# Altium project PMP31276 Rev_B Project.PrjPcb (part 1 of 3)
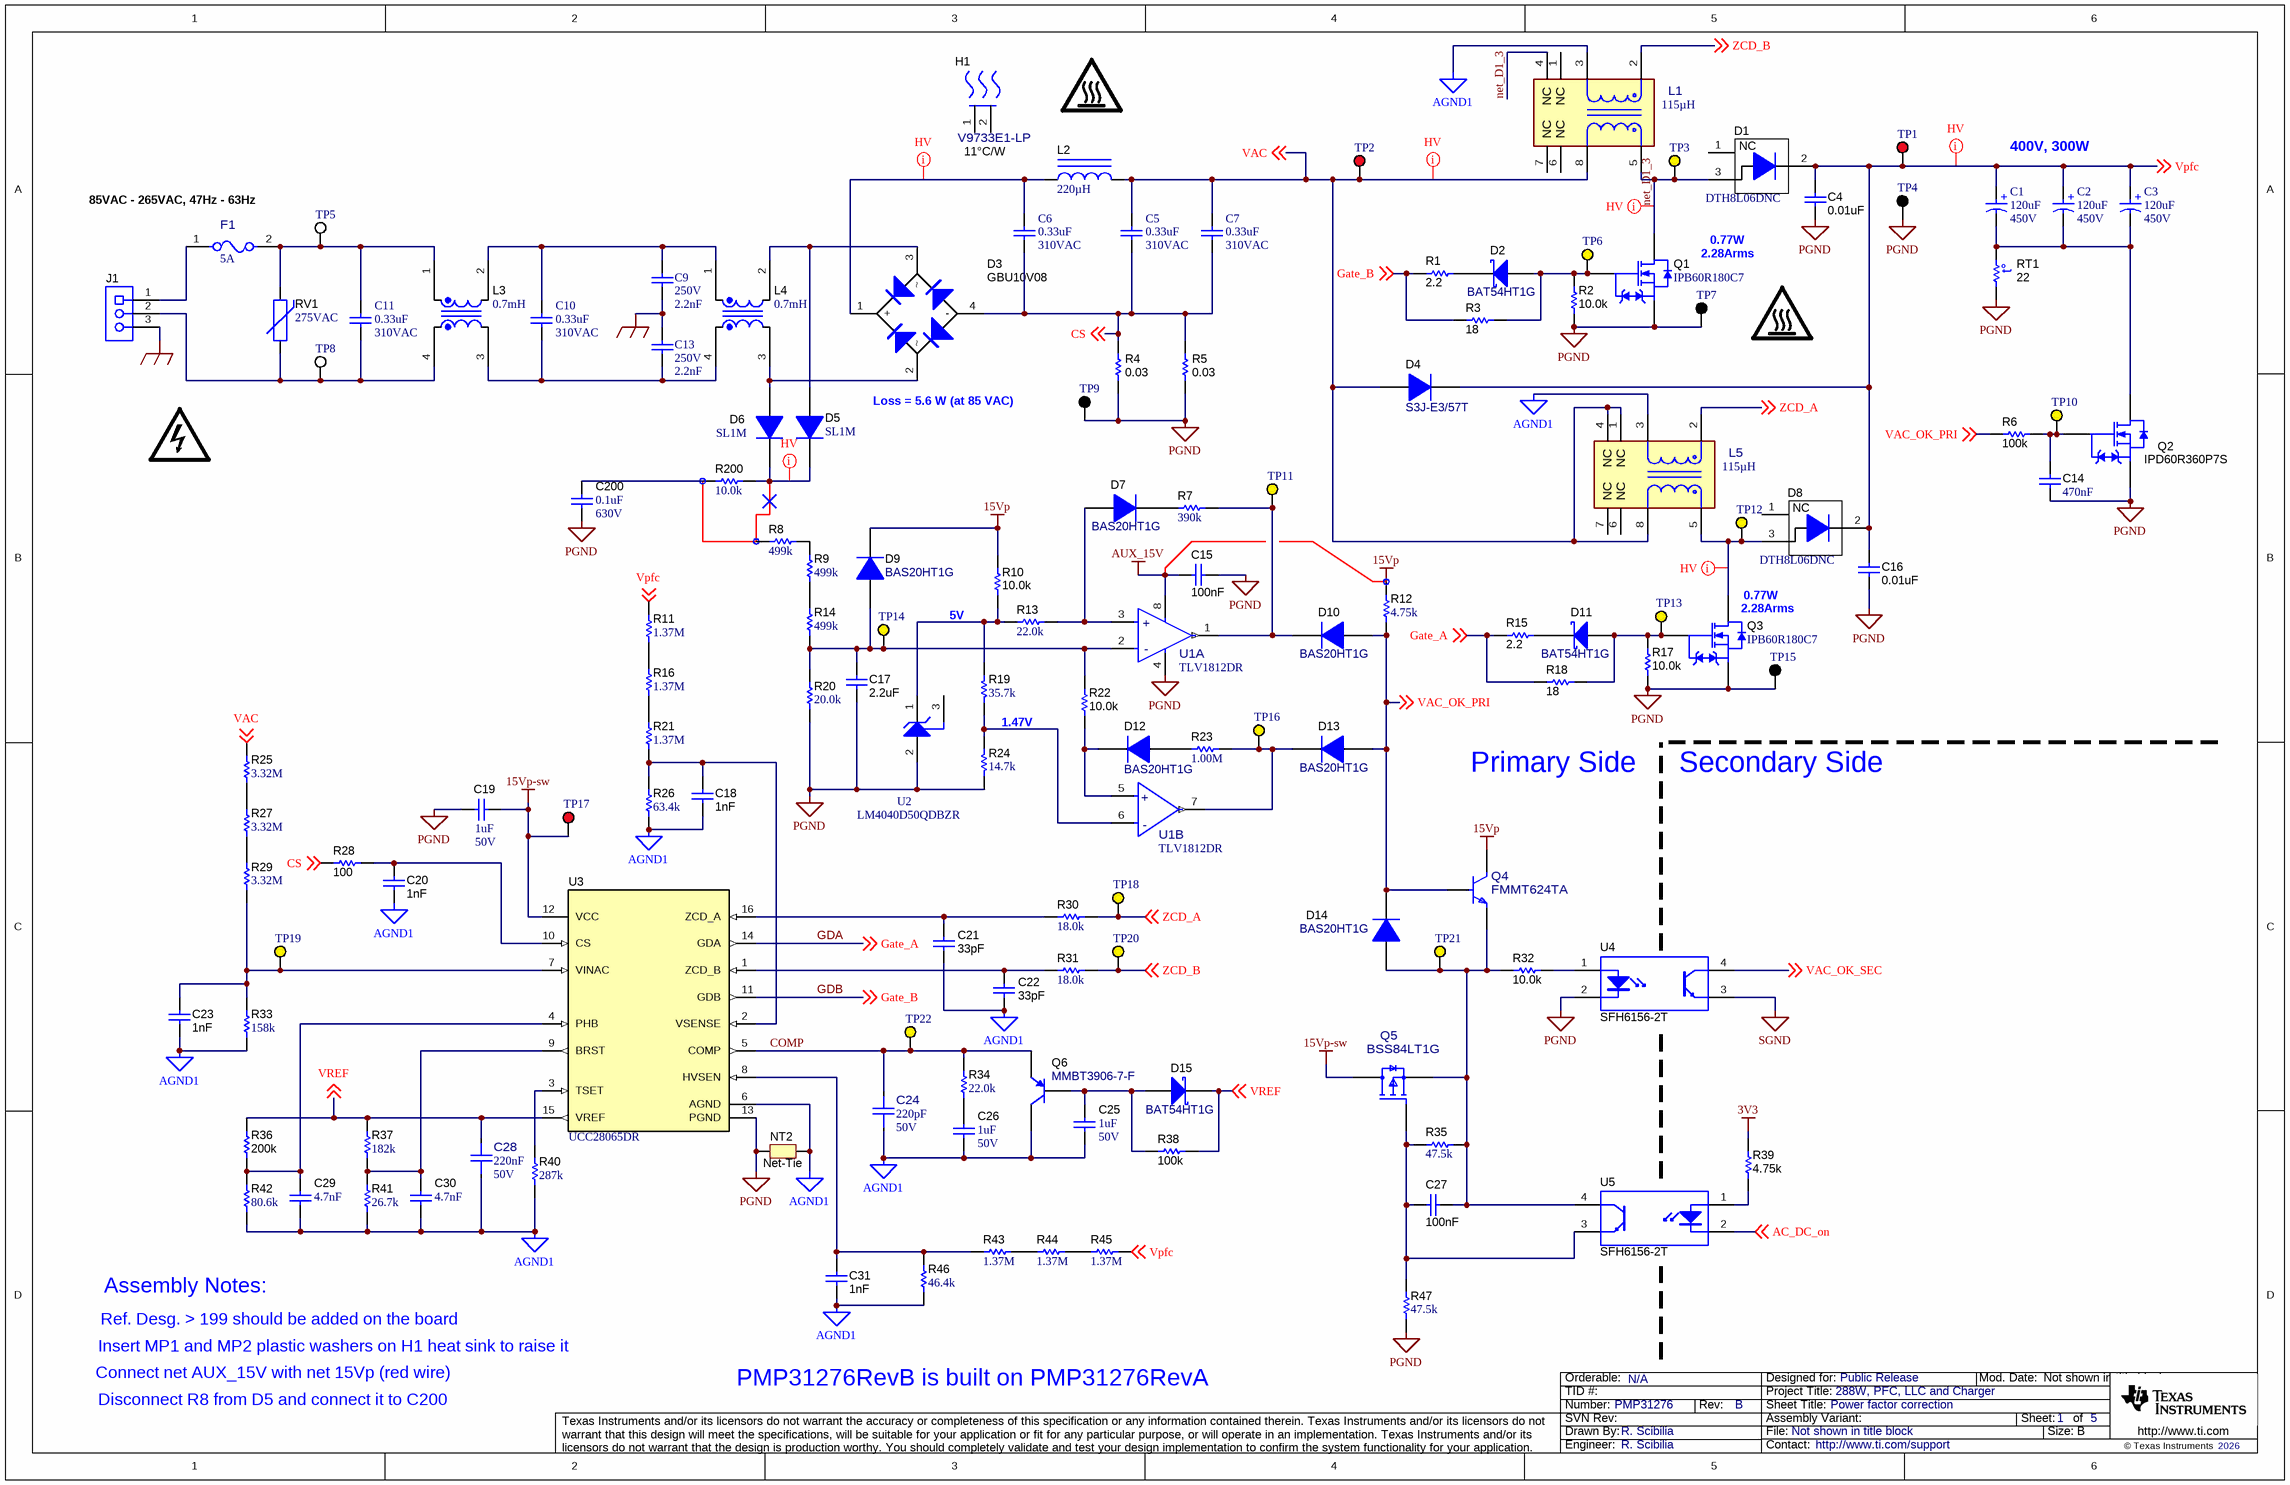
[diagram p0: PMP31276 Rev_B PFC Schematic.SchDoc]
CopyrightYear: 2026; EVM_orderable: N/A; PCB_Layout: N/A; PCB_Rev: A; PRJ_Customer: Public Release; PRJ_Engineer: R. Scibilia; PRJ_Number: PMP31276; PRJ_Title: 288W, PFC, LLC and Charger; SCH_Rev: B; TechSupport: http://www.ti.com/support
5 sheets, 390 parts. Net scope: global (net labels, ports and power ports of the same name join across sheets).
Board file: PMP31276 Rev_A PCB.PcbDoc
Sheets:
  PMP31276 Rev_B PFC Schematic.SchDoc
  PMP31276 Rev_B LLC Schematic.SchDoc
  PMP31276 Rev_B Charger Schematic.SchDoc
  PMP31276 Rev_B LaunchPad Schematic.SchDoc
  PMP31276 Rev_B Hardware.SchDoc

## Sheet PMP31276 Rev_B PFC Schematic.SchDoc: Power factor correction
size 431 x 279 mm; Date: Not shown in title block; ApprovedBy: Not shown in title block; CheckedBy: Not shown in title block; Author: Not shown in title block; CompanyName: Not shown in title block; DrawnBy: R. Scibilia; Engineer: R. Scibilia; Organization: Not shown in title block; Address1: Not shown in title block; Address2: Not shown in title block; Address3: Not shown in title block; Address4: Not shown in title block; DocumentNumber: 1; Revision: Use project parameter SCH_Rev; SheetNumber: 1; SheetTotal: 5; PageSetup: Record=PageOptions¦CenterHorizontal=True¦CenterVertical=True¦PrintScale=1.00¦XCorrection=1.00¦YCorrection=1.00¦PrintKind=0¦BorderSize=5000000¦LeftOffset=0¦BottomOffset=0¦Orientation=2¦PaperLength=1000¦PaperWidth=1000¦Scale=100¦PaperSource=15¦PrintQuality=600¦MediaType=1¦DitherType=10¦PaperKind=Letter¦PrintScaleMode=1

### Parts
(Parts that share a designator on the sheet are numbered #1, #2 ... from top to bottom, then left to right.)
C1  value 120uF  Rated Voltage (DC): 450V  [WCAP-AI3H_D25H30]  (hidden comment: 861141484010)
C2  value 120uF  Rated Voltage (DC): 450V  [WCAP-AI3H_D25H30]  (hidden comment: 861141484010)
C3  value 120uF  Rated Voltage (DC): 450V  [WCAP-AI3H_D25H30]  (hidden comment: 861141484010)
C4  ValueDisplayed: 0.01uF  [1210]  (hidden comment: 885342208009)
C5  value 0.33uF  Rated Voltage (AC): 310VAC  [WCAP-FTXX_L15W8.5H14]  (hidden comment: 890334024003)
C6  value 0.33uF  Rated Voltage (AC): 310VAC  [WCAP-FTXX_L15W8.5H14]  (hidden comment: 890334024003)
C7  value 0.33uF  Rated Voltage (AC): 310VAC  [WCAP-FTXX_L15W8.5H14]  (hidden comment: 890334024003)
C9  value 2.2nF  Rated Voltage (AC): 250V  [WCAP-CSSA_2211_L5.7W2.8H2.5]  (hidden comment: 8853522130151)
C10  value 0.33uF  Rated Voltage (AC): 310VAC  [WCAP-FTXX_L15W8.5H14]  (hidden comment: 890334024003)
C11  value 0.33uF  Rated Voltage (AC): 310VAC  [WCAP-FTXX_L15W8.5H14]  (hidden comment: 890334024003)
C13  value 2.2nF  Rated Voltage (AC): 250V  [WCAP-CSSA_2211_L5.7W2.8H2.5]  (hidden comment: 8853522130151)
C14  Cap_F: 470nF  [0603]  (hidden comment: GRM188R71E474KA12D)
C15  Cap_F: 100nF  [0603]  (hidden comment: 885012206095)
C16  ValueDisplayed: 0.01uF  [1210]  (hidden comment: 885342208009)
C17  ValueDisplayed: 2.2uF  [0603]  (hidden comment: GRM188R6YA225KA12D)
C18  Cap_F: 1nF  [0603]  (hidden comment: 885012206083)
C19  VDC_V: 50V  ValueDisplayed: 1uF  [0603]  (hidden comment: C1608X6S1H105K080AC)
C20  Cap_F: 1nF  [0603]  (hidden comment: 885012206083)
C21  ValueDisplayed: 33pF  [0603]  (hidden comment: 885012006054)
C22  ValueDisplayed: 33pF  [0603]  (hidden comment: 885012006054)
C23  Cap_F: 1nF  [0603]  (hidden comment: 885012206083)
C24  ValueDisplayed: 220pF  VDC_V: 50V  [FP-C0603C221J5GAC7867_0603-IPC_B]  (hidden comment: C0603C221J5GAC7867)
C25  VDC_V: 50V  ValueDisplayed: 1uF  [0603]  (hidden comment: C1608X6S1H105K080AC)
C26  VDC_V: 50V  ValueDisplayed: 1uF  [0603]  (hidden comment: C1608X6S1H105K080AC)
C27  Cap_F: 100nF  [0603]  (hidden comment: 885012206095)
C28  Cap_F: 220nF  VDC_V: 50V  [FP-885012206125_0603-IPC_B]  (hidden comment: 885012206125)
C29  Cap_F: 4.7nF  [0603]  (hidden comment: 885012206087)
C30  Cap_F: 4.7nF  [0603]  (hidden comment: 885012206087)
C31  Cap_F: 1nF  [0603]  (hidden comment: 885012206083)
C200  VDC_V: 630V  ValueDisplayed: 0.1uF  [1210_280]  (hidden comment: C1210C104KBRAC7800)
D1  DTH8L06DNC  [DPAK]
D2  BAT54HT1G  [SOD-323]
D3  GBU10V08  [GBU]
D4  S3J-E3/57T  [SMC]
D5  SL1M  [SOD-123F]
D6  SL1M  [SOD-123F]
D7  BAS20HT1G  [SOD-323]
D8  DTH8L06DNC  [DPAK]
D9  BAS20HT1G  [SOD-323]
D10  BAS20HT1G  [SOD-323]
D11  BAT54HT1G  [SOD-323]
D12  BAS20HT1G  [SOD-323]
D13  BAS20HT1G  [SOD-323]
D14  BAS20HT1G  [SOD-323]
D15  BAT54HT1G  [SOD-323]
F1  value 5A  [FP-SF-3812F1500T-2_3812-MFG]  (hidden comment: SF-3812F500T-2)
H1  V9733E1-LP  Thermal Resistance Natural Convection: 11°C/W  [FP-V9733E1-LP_THERMAL_HEATSINK_25MM0_42MM0-MFG]
J1  691213510003  [On-Shore_ED120_3DS]  (value not drawn)
L1  Ind_H: 115µH  [FP-750314724_PTH_XFRMR_23MM5_26MM0-MFG]  (hidden comment: 750314724)
L2  ValueDisplayed: 220µH  [WE-HCF Round_2920]  (hidden comment: 74437529203221)
L3  value 0.7mH  [Wurth_7446631007]  (hidden comment: 74466340007)
L4  value 0.7mH  [Wurth_7446631007]  (hidden comment: 74466340007)
L5  Ind_H: 115µH  [FP-750314724_PTH_XFRMR_23MM5_26MM0-MFG]  (hidden comment: 750314724)
LOGO?#1  CAUTION HOT SURFACE  [IEC_HotSurface_Small]  (value not drawn)  (graphical)
LOGO?#2  CAUTION HOT SURFACE  [IEC_HotSurface_Small]  (value not drawn)  (graphical)
LOGO?#3  DANGER HIGH VOLTAGE  [IEC_HighVoltage_Small]  (value not drawn)  (graphical)
NT2  Net-Tie  [Net-Tie_20milWide_60milLong]  (net tie, no BOM)
Q1  IPB60R180C7  [DDPAK]
Q2  value IPD60R360P7S  [DPAK]  (hidden comment: IPD60R360P7SAUMA1)
Q3  IPB60R180C7  [DDPAK]
Q4  FMMT624TA  [FP-FMMT624TA_SOT23-MFG]
Q5  BSS84LT1G  [FP-BSS84LT1G_SOT-23-3-318-08-MFG]
Q6  MMBT3906-7-F  [SOT-23]
R1  ValueDisplayed: 2.2  [0805_HV]  (hidden comment: RC0805JR-072R2L)
R2  ValueDisplayed: 10.0k  [0603]  (hidden comment: Resistor)
R3  ValueDisplayed: 18  [0805_HV]  (hidden comment: ERJ-6GEYJ180V)
R4  ValueDisplayed: 0.03  [2512]  (hidden comment: Resistor)
R5  ValueDisplayed: 0.03  [2512]  (hidden comment: Resistor)
R6  ValueDisplayed: 100k  [0603]  (hidden comment: CRCW0603100KFKEA)
R7  ValueDisplayed: 390k  [0603]  (hidden comment: RC0603FR-07390KL)
R8  ValueDisplayed: 499k  [1206]  (hidden comment: RC1206FR-07499KL)
R9  ValueDisplayed: 499k  [1206]  (hidden comment: RC1206FR-07499KL)
R10  ValueDisplayed: 10.0k  [0603]  (hidden comment: Resistor)
R11  ValueDisplayed: 1.37M  [1206]  (hidden comment: CRCW12061M37FKEA)
R12  ValueDisplayed: 4.75k  [0603]  (hidden comment: RC0603FR-074K75L)
R13  ValueDisplayed: 22.0k  [0603]  (hidden comment: RC0603FR-0722KL)
R14  ValueDisplayed: 499k  [1206]  (hidden comment: RC1206FR-07499KL)
R15  ValueDisplayed: 2.2  [0805_HV]  (hidden comment: RC0805JR-072R2L)
R16  ValueDisplayed: 1.37M  [1206]  (hidden comment: CRCW12061M37FKEA)
R17  ValueDisplayed: 10.0k  [0603]  (hidden comment: Resistor)
R18  ValueDisplayed: 18  [0805_HV]  (hidden comment: ERJ-6GEYJ180V)
R19  ValueDisplayed: 35.7k  [0603]  (hidden comment: RC0603FR-0735K7L)
R20  ValueDisplayed: 20.0k  [0603]  (hidden comment: ERJ-3EKF2002V)
R21  ValueDisplayed: 1.37M  [1206]  (hidden comment: CRCW12061M37FKEA)
R22  ValueDisplayed: 10.0k  [0603]  (hidden comment: Resistor)
R23  ValueDisplayed: 1.00M  [0603]  (hidden comment: RC0603FR-071ML)
R24  ValueDisplayed: 14.7k  [0603]  (hidden comment: RC0603FR-0714K7L)
R25  ValueDisplayed: 3.32M  [1206]  (hidden comment: CRCW12063M32FKEA)
R26  ValueDisplayed: 63.4k  [0603]  (hidden comment: RC0603FR-0763K4L)
R27  ValueDisplayed: 3.32M  [1206]  (hidden comment: CRCW12063M32FKEA)
R28  ValueDisplayed: 100  [0603]  (hidden comment: Resistor)
R29  ValueDisplayed: 3.32M  [1206]  (hidden comment: CRCW12063M32FKEA)
R30  ValueDisplayed: 18.0k  [0805_HV]  (hidden comment: RC0805FR-0718KL)
R31  ValueDisplayed: 18.0k  [0805_HV]  (hidden comment: RC0805FR-0718KL)
R32  ValueDisplayed: 10.0k  [0603]  (hidden comment: Resistor)
R33  ValueDisplayed: 158k  [0603]  (hidden comment: RC0603FR-07158KL)
R34  ValueDisplayed: 22.0k  [0603]  (hidden comment: RC0603FR-0722KL)
R35  ValueDisplayed: 47.5k  [0603]  (hidden comment: RC0603FR-0747K5L)
R36  ValueDisplayed: 200k  [0603]  (hidden comment: RC0603FR-07200KL)
R37  ValueDisplayed: 182k  [0603]  (hidden comment: RC0603FR-07182KL)
R38  ValueDisplayed: 100k  [0603]  (hidden comment: CRCW0603100KFKEA)
R39  ValueDisplayed: 4.75k  [0603]  (hidden comment: RC0603FR-074K75L)
R40  ValueDisplayed: 287k  [0603]  (hidden comment: RC0603FR-07287KL)
R41  ValueDisplayed: 26.7k  [0603]  (hidden comment: RC0603FR-0726K7L)
R42  ValueDisplayed: 80.6k  [0603]  (hidden comment: RC0603FR-0780K6L)
R43  ValueDisplayed: 1.37M  [1206]  (hidden comment: CRCW12061M37FKEA)
R44  ValueDisplayed: 1.37M  [1206]  (hidden comment: CRCW12061M37FKEA)
R45  ValueDisplayed: 1.37M  [1206]  (hidden comment: CRCW12061M37FKEA)
R46  ValueDisplayed: 46.4k  [0603]  (hidden comment: RC0603FR-0746K4L)
R47  ValueDisplayed: 47.5k  [0603]  (hidden comment: RC0603FR-0747K5L)
R200  ValueDisplayed: 10.0k  [1206]  (hidden comment: ERJ-8ENF1002V)
RT1  value 22  [S237]  (hidden comment: B57237S0220M000)
RV1  value 275VAC  [VAR_SM7-Series_H]  (hidden comment: V275SM7)
TP1  5000  [Keystone5000]  (value not drawn)
TP2  5000  [Keystone5000]  (value not drawn)
TP3  5004  [Keystone5004]  (value not drawn)
TP4  5001  [Keystone5001]  (value not drawn)
TP5  5002  [Keystone5002]  (value not drawn)
TP6  5004  [Keystone5004]  (value not drawn)
TP7  5001  [Keystone5001]  (value not drawn)
TP8  5002  [Keystone5002]  (value not drawn)
TP9  5001  [Keystone5001]  (value not drawn)
TP10  5004  [Keystone5004]  (value not drawn)
TP11  5004  [Keystone5004]  (value not drawn)
TP12  5004  [Keystone5004]  (value not drawn)
TP13  5004  [Keystone5004]  (value not drawn)
TP14  5004  [Keystone5004]  (value not drawn)
TP15  5001  [Keystone5001]  (value not drawn)
TP16  5004  [Keystone5004]  (value not drawn)
TP17  5000  [Keystone5000]  (value not drawn)
TP18  5004  [Keystone5004]  (value not drawn)
TP19  5004  [Keystone5004]  (value not drawn)
TP20  5004  [Keystone5004]  (value not drawn)
TP21  5004  [Keystone5004]  (value not drawn)
TP22  5004  [Keystone5004]  (value not drawn)
U1  TLV1812DR  [D0008A-MFG]  (parts A,B of 2)
U2  LM4040D50QDBZR  [DBZ0003A_N]
U3  UCC28065DR  [D0016A_N]
U4  SFH6156-2T  [SMD-4]
U5  SFH6156-2T  [SMD-4]

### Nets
3V3: R39.2
15Vp: D9.1(K) Q4.3(C) R10.2 R12.2
15Vp-sw: C19.1 Q5.3(D) TP17.1 U3.12(VCC)
AGND1: C18.2 C20.2 C21.2 C22.2 C23.2 C24.1 C25.2 C26.2 C28.1 C29.2 C30.2 C31.2 L1.3 L5.3 NT2.2 Q6.3(C) R26.1 R33.1 R40.1 R41.1 R42.1 R46.1 U3.6(AGND)
AUX_15V: C15.1 U1.8(V+)
EARTH: C9.2 C13.1 J1.3
PGND: C4.2 C14.2 C15.2 C16.2 C17.2 C19.2 C200.2 NT2.1 Q1.3(S) Q2.3(S) Q3.3(S) R2.1 R4.1 R5.1 R17.1 R20.1 R24.1 R47.2 RT1.1 TP4.1 TP7.1 TP9.1 TP15.1 U1.4(V-) U2.2(ANODE) U3.13(PGND) U4.2(K)
SGND: U4.3(E)
AC_DC_on: U5.2(K) ; off-sheet AC_DC_on
COMP: C24.2 Q6.2(E) R34.2 TP22.1 U3.5(COMP)
CS: C5.1 C6.1 C7.1 D3.4(-) R4.2 R5.2 R28.1 ; off-sheet CS
GDA: R15.1 R18.1 U3.14(GDA) ; off-sheet Gate_A  [also labelled Gate_A]
GDB: R1.1 R3.1 U3.11(GDB) ; off-sheet Gate_B  [also labelled Gate_B]
net_D1_3: D1.3(A) L1.4(NC) L1.5 Q1.2(D) TP3.1
VAC: C5.2 C7.2 D4.2(A) L1.8 L2.2 L5.1(NC) L5.4(NC) L5.8 R25.2 TP2.1 ; off-sheet VAC
VAC_OK_PRI: D10.2(A) D13.2(A) D14.1(K) Q4.1(B) R6.2 R12.1 ; off-sheet VAC_OK_PRI
VAC_OK_SEC: U4.4(C) ; off-sheet VAC_OK_SEC
Vpfc: C1.1(P) C2.1(P) C3.1(P) C4.1 C16.1 D1.2(K) D4.1(K) D8.2(K) R11.2 R45.1 TP1.1 ; off-sheet Vpfc
VREF: C28.2 D15.1(K) R36.2 R37.2 R38.1 U3.15(VREF) ; off-sheet VREF
ZCD_A: L5.2 R30.2 TP18.1 ; off-sheet ZCD_A
ZCD_B: L1.2 R31.2 TP20.1 ; off-sheet ZCD_B
NetC1_2: C1.2(N) C2.2(N) C3.2(N) Q2.2(D) RT1.2
NetC6_2: C6.2 D3.1(+) L2.1
NetC9_1: C9.1 C10.2 L3.2 L4.1
NetC10_1: C10.1 C13.2 L3.3 L4.4
NetC11_1: C11.1 J1.2 L3.4 RV1.1 TP8.1
NetC11_2: C11.2 F1.2 L3.1 RV1.2 TP5.1
NetC14_1: C14.1 Q2.1(G) R6.1 TP10.1
NetC17_1: C17.1 D9.2(A) R14.1 R20.2 R22.2 TP14.1 U1.2(-IN_A)
NetC18_1: C18.1 R21.1 R26.2 U3.2(VSENSE)
NetC20_1: C20.1 R28.2 U3.10(CS)
NetC21_1: C21.1 R30.1 U3.16(ZCD_A)
NetC22_1: C22.1 R31.1 U3.1(ZCD_B)
NetC23_1: C23.1 R29.1 R33.2 TP19.1 U3.7(VINAC)
NetC25_1: C25.1 D15.2(A) Q6.1(B) R38.2
NetC26_1: C26.1 R34.1
NetC27_1: C27.1 Q5.1(G) R35.2 R47.1 U5.3(E)
NetC27_2: C27.2 D14.2(A) Q4.2(E) Q5.2(S) R32.2 R35.1 TP21.1 U5.4(C)
NetC29_1: C29.1 R36.1 R42.2 U3.4(PHB)
NetC30_1: C30.1 R37.1 R41.2 U3.9(BRST)
NetC31_1: C31.1 R43.2 R46.2 U3.8(HVSEN)
NetC200_1: C200.1 R200.2
NetD2_1: D2.1(K) R1.2
NetD2_2: D2.2(A) Q1.1(G) R2.2 R3.2 TP6.1
NetD3_2: D3.2 D6.2(A) L4.3
NetD3_3: D3.3 D5.2(A) L4.2
NetD5_1: D5.1(K) D6.1(K) R200.1
NetD7_1: D7.1(K) R7.1
NetD7_2: D7.2(A) R13.2 U1.3(+IN_A)
NetD8_3: D8.3(A) L5.5 Q3.2(D) TP12.1
NetD10_1: D10.1(K) R7.2 TP11.1 U1.1(OUT_A)
NetD11_1: D11.1(K) R15.2
NetD11_2: D11.2(A) Q3.1(G) R17.2 R18.2 TP13.1
NetD12_1: D12.1(K) R22.1 U1.5(+IN_B)
NetD12_2: D12.2(A) R23.1
NetD13_1: D13.1(K) R23.2 TP16.1 U1.7(OUT_B)
NetF1_1: F1.1 J1.1
NetR8_1: R8.1 R9.2
NetR9_1: R9.1 R14.2
NetR10_1: R10.1 R13.1 R19.2 U2.1(CATHODE)
NetR11_1: R11.1 R16.2
NetR16_1: R16.1 R21.2
NetR19_1: R19.1 R24.2 U1.6(-IN_B)
NetR25_1: R25.1 R27.2
NetR27_1: R27.1 R29.2
NetR32_1: R32.1 U4.1(A)
NetR39_1: R39.1 U5.1(A)
NetR40_2: R40.2 U3.3(TSET)
NetR43_1: R43.1 R44.2
NetR44_1: R44.1 R45.2

Not connected (* = marked no-connect by the designer): D1 1(NC); D8 1(NC); H1 1(MNT_1) 2(MNT_2); L1 1(NC) 6(NC) 7(NC); L5 6(NC) 7(NC); R8 2; U2 3(NC)

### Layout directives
net class HV: net_D1_3, NetC6_2, NetD5_1, NetD8_3, VAC, Vpfc

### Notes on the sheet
- 400V, 300W
- (near F1) 85VAC - 265VAC, 47Hz - 63Hz
- 2.28Arms
- 0.77W
- Loss = 5.6 W (at 85 VAC)
- 5V
- (near Q3) 0.77W
- (near Q3) 2.28Arms
- 1.47V
- Primary Side
- Secondary Side
- Assembly Notes:
- Connect net AUX_15V with net 15Vp (red wire)
- Ref. Desg. > 199 should be added on the board
- Insert MP1 and MP2 plastic washers on H1 heat sink to raise it
- Disconnect R8 from D5 and connect it to C200
- PMP31276RevB is built on PMP31276RevA

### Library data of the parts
C1-C3 = CMP-0110395-1: WCAP-AI3H Aluminum Electrolytic Capacitor, Snap-In, D25 x H30mm, 120µF, 450V; Manufacturer: Wurth Elektronik; Capacitance Tolerance: +/-20%; Dissipation Factor: 20%; Endurance: 3000h; Leakage Current: 697.14uA; Ripple Current: 800mA; Technical Reference: ANJO300121M450DSIC3C000
C4 C16 = CMP-0009273-2: CAP, CERM, 0.01 uF, 500 V, +/- 10%, X7R, 1206; Manufacturer: Wuerth; TaMin_C: -55°C; Polarized: N; SizeAreaWB_mm2: 14.7; Value1: Unknown; U/M: EA; Value: 0.01uF; TaMax_C: 125°C; SizeZ_mm: 1.35; SizeX_mm: 3.2; SizeY_mm: 2.5; Cap_Case: 1206; Value2: 500V; SizeArea_mm2: 8; Cap_F: 10nF; AEC Category: Q200
C5-C7 C10 C11 = CMP-0108923-1: WCAP-FTXX Film Capacitor, THT, L15 x W8.5 x H14mm, 330nF, 310V; Manufacturer: Wurth Elektronik; Capacitance Tolerance: +/-10%; Dissipation Factor @100kHz: 2%; Dissipation Factor @10kHz: 0.2%; Dissipation Factor @1kHz: 0.1%; Insulation Resistance: 30000MOhm; Pitch: 12.5mm; Rate of Voltage Rise: 260V/us; Technical Reference: MX2P125334K275ASPB15000
C9 C13 = CMP-0112567-1: WCAP-CSSA Multilayer Ceramic Chip Safety Capacitor, size 2211, X7R Class II, 2.2nF, 250VAC; Manufacturer: Wurth Elektronik; Capacitance Tolerance: +/-10%; Case/Size Code: 2211; Dissipation Factor: 2.5%; Impulse Voltage: 5000VDC; Insulation Resistance: 10GOhm; Safety Class: X1/Y2; Technical Reference: X7R2211222KE00IFCT1B000
C14 = CMP-0007424-4: CAP, CERM, 0.47 uF, 25 V, +/- 10%, X7R, 0603; Manufacturer: MuRata; TaMin_C: -55°C; Polarized: N; SizeAreaWB_mm2: 4.68; Value1: Unknown; U/M: EA; Value: 0.47uF; TaMax_C: 125°C; SizeZ_mm: 1; SizeX_mm: 1.6; SizeY_mm: 0.8; Value2: 25V; SizeArea_mm2: 1.28; AEC Category: Q200
C15 C27 = CMP-0006837-3: CAP, CERM, 0.1 uF, 50 V, +/- 10%, X7R, 0603; Manufacturer: Wurth Elektronik; TaMin_C: -55°C; Polarized: N; SizeAreaWB_mm2: 4.68; Value1: Unknown; U/M: EA; Value: 0.1uF; TaMax_C: 125°C; SizeZ_mm: 1; SizeX_mm: 1.6; SizeY_mm: 0.8; Value2: 50V; SizeArea_mm2: 1.28; AEC Category: Q200
C17 = CMP-0007356-5: CAP, CERM, 2.2 uF, 35 V, +/- 10%, X5R, 0603; Manufacturer: MuRata; TaMin_C: -55°C; Polarized: N; SizeAreaWB_mm2: 4.68; Value1: Unknown; U/M: EA; Value: 2.2uF; TaMax_C: 85°C; SizeZ_mm: 1; SizeX_mm: 1.6; SizeY_mm: 0.8; Value2: 35V; SizeArea_mm2: 1.28; CompType: Capacitor; Cap_F: 2.2µF; AEC Category: Q200
C18 C20 C23 C31 = CMP-0064933-4: CAP, CERM, 1000 pF, 50 V,+/- 10%, X7R, 0603; Manufacturer: Wurth Elektronik; TaMin_C: -55°C; Polarized: N; SizeAreaWB_mm2: 4.68; Value1: Unknown; U/M: EA; Value: 1000pF; TaMax_C: 125°C; SizeZ_mm: 1; SizeX_mm: 1.6; SizeY_mm: 0.8; Value2: 50V; SizeArea_mm2: 1.28; AEC Category: Q200
C19 C25 C26 = CMP-0007029-4: CAP, CERM, 1 uF, 50 V, +/- 10%, X6S, 0603; Manufacturer: TDK; TaMin_C: -55°C; ESR_ohm: 5.522m; Polarized: N; SizeAreaWB_mm2: 4.68; Value1: 0.005522 ohm; U/M: EA; Value: 1uF; TaMax_C: 105°C; SizeZ_mm: 1; SizeX_mm: 1.6; SizeY_mm: 0.8; SizeArea_mm2: 1.28; Cap_F: 1µF; IRMS_A: 2.2162A; AEC Category: Q200
C21 C22 = CMP-0006919-4: CAP, CERM, 33 pF, 50 V, +/- 5%, C0G/NP0, 0603; Manufacturer: Wuerth; TaMin_C: -55°C; Polarized: N; SizeAreaWB_mm2: 4.68; Value1: Unknown; U/M: EA; Value: 33pF; TaMax_C: 125°C; SizeZ_mm: 1; SizeX_mm: 1.6; SizeY_mm: 0.8; Value2: 50V; SizeArea_mm2: 1.28; AEC Category: Q200
C24 = CMP-0045670-1: 220 pF ±5% 50V Ceramic Capacitor C0G, NP0 0603 (1608 Metric); Manufacturer: KEMET; AEC Qualified: No; SizeZ_mm: 0.87mm; TempCo: 30ppm/°C; Value: 220pF
C28 = CMP-0049212-1: 0.22 µF ±5% 50V Ceramic Capacitor X7R 0603 (1608 Metric); Manufacturer: Wurth Electronics; AEC Qualified: No; SizeZ_mm: 0.95mm; TempCo: 15%; Value: 220nF
C29 C30 = CMP-0006835-4: CAP, CERM, 4700 pF, 50 V, +/- 10%, X7R, 0603; Manufacturer: Wurth Elektronik; TaMin_C: -55°C; Polarized: N; SizeAreaWB_mm2: 4.68; Value1: Unknown; U/M: EA; Value: 4700pF; TaMax_C: 125°C; SizeZ_mm: 1; SizeX_mm: 1.6; SizeY_mm: 0.8; Value2: 50V; SizeArea_mm2: 1.28; AEC Category: Q200
C200 = CMP-0009076-1: CAP, CERM, 0.1 uF, 630 V, +/- 10%, X7R, 1210; Manufacturer: Kemet; TaMin_C: -55°C; Polarized: N; SizeAreaWB_mm2: 14.7; Value1: Unknown; U/M: EA; Value: 0.1uF; TaMax_C: 125°C; SizeZ_mm: 2.8; SizeX_mm: 3.2; SizeY_mm: 2.5; Cap_Case: 1210; SizeArea_mm2: 8; Cap_F: 100nF; AEC Category: Q200
D1 D8 = CMP-0079155-3: Diode, Ultrafast, 600 V, 8 A, DPAK; Manufacturer: Diodes; Vf_V: 1.05V; AEC Qualified: N; Value1: 8A; SizeY_mm: 6.54; SizeAreaWB_mm2: 101.7114; SizeArea_mm2: 64.8114; Vr_V: 600V; SizeX_mm: 9.91; TJmax_C: 175°C; RJC_CperW: 3.2; SizeZ_mm: 2.29; AEC Category: Q101
D2 D11 D15 = CMP-0028455-2: Diode, Schottky, 30 V, 0.2 A, SOD-323; Manufacturer: ON Semiconductor; Vr_V: 30V; SizeZ_mm: 1; Value1: 0.2A; SizeAreaWB_mm2: 8.695; Vf_V: 350mV; Io_A: 200mA; SizeX_mm: 2.7; SizeY_mm: 1.35; Green_Lifecycle: Active; AEC Category: Q101; Value2: 0.35V; SizeArea_mm2: 3.645; Green_REACh: Passed
D3 = CMP-0029234-3: Diode, Switching-Bridge, 800 V, 10 A, TH; Manufacturer: Diodes Inc.; SizeZ_mm: 21.55; Vf_V: 1V; RJC_CperW: 2.2; SizeX_mm: 22.05; Value: 800V; SizeArea_mm2: 75.6315; Io_A: 10A; Green_Lifecycle: Not Set; AEC Category: Q101; SizeAreaWB_mm2: 130.5915; SizeY_mm: 3.43; Green_REACh: Incomplete
D4 = CMP-0082070-2: Diode, Switching, 600 V, 3 A, SMC; Manufacturer: Vishay-Semiconductor; SizeArea_mm2: 50.5686; Value2: 1.15V; RJC_CperW: 13; SizeY_mm: 6.22; TJmax_C: 150°C; SizeAreaWB_mm2: 83.2686; Io_A: 3A; AEC Category: Q101; SizeZ_mm: 2.62; Vr_V: 600V; AEC Qualified: N; SizeX_mm: 8.13
D5 D6 = CMP-0082234-2: Diode, Fast Rectifier, 1000 V, 1 A, SOD-123F; Manufacturer: Diotech Semiconductor AG; SizeX_mm: 3.5; Vf_V: 1.3V; SizeZ_mm: 1.1; TJmax_C: 150°C; SizeY_mm: 1.6; AEC Category: Q101; Io_A: 1A; AEC Qualified: N; SizeArea_mm2: 5.6; Vr_V: 1kV; Type: Standard Recovery Rectifier; RJC_CperW: 10; SizeAreaWB_mm2: 11.7
D7 D9 D10 D12-D14 = CMP-0029150-2: Diode, Switching, 200 V, 0.2 A, AEC-Q101, SOD-323; Manufacturer: ON Semiconductor; Value2: 1.25V; Value1: 0.2A; SizeZ_mm: 1; Green_REACh: Incomplete; SizeArea_mm2: 3.645; Vr_V: 200V; SizeX_mm: 2.7; TJmax_C: 150°C; Io_A: 200mA; Green_Lifecycle: Not Set; SizeAreaWB_mm2: 8.695; AEC Qualified: Y; AEC Category: Q101; SizeY_mm: 1.35
F1 = CMP-0037653-1: 5 A 250 V AC 80 V DC Fuse Board Mount (Cartridge Style Excluded) Surface Mount 2-SMD, Square End Block; Manufacturer: Bourns; Interrupt_AC: 50A; SizeZ_mm: 3.3mm; VAC_V: 250V; Fuse Speed: Slow; AEC Qualified: No
H1 = CMP-0092962-1: Heat Sink 11 K/W, 25,4x42x25 mm, black anodized, for TO-220; Manufacturer: Assmann WSW components; SizeZ_mm: 25.4mm; AEC Qualified: No
J1 = CMP-0074911-1: Terminal Block, 5.08 mm, 3x1, Brass, TH; Manufacturer: Wuerth; Cert_VDE: Y; CNHeader: False; Current_A: 14A; Green_Lifecycle: Not Set; Shrouded: N; Gender: Female; Green_REACh: Incomplete; Voltage_V: 300V; Row_Count: 1; Pitch_mm: 5.08; CT: True
L1 L5 = CMP-0120631-1: INDUCTOR; Manufacturer: Wurth; DCR_ohm: 80m; Ns1toNp: 10:1; Rsec1_ohm: 30m; SizeZ_mm: 29.5mm; AEC Qualified: No; Voltage_Isolation_Vrms: 1kV
L2 = CMP-0085391-1: Inductor, Shielded, Mn-Zn, 220 µH, 5.3 A, 0.040095 ohm, SMD; Manufacturer: Wurth Elektronik; AEC Qualified: N; Value: 220uH; Imax_A: 5.3A; SizeZ_mm: 20.5; Irms: 8.8A @ 50C rise; SizeAreaWB_mm2: 810; AEC Category: Q200; DCR_ohm: 40.095m; SizeX_mm: 25; Isat: 5.3A @ 30% inductance drop; SizeY_mm: 28; SizeArea_mm2: 700
L3 L4 = CMP-0013106-2: Coupled inductor, 0.7 mH, 5.25 A, 0.03 ohm, SMD; Manufacturer: Wurth Elektronik; DCR_ohm: 0.03
LOGO?#1 LOGO?#2 = IEC_HotSurface: IEC 61010-1 Hot Surface Warning; SymbolCreator: a0412235
LOGO?#3 = IEC_HighVoltage: IEC 61010-1 High Voltage Warning; SymbolCreator: a0412235
NT2 = CMP-0078142-6: Single point connection between nets.
Q1 Q3 = CMP-0086154-1: MOSFET, N-CH, 600 V, 13 A, DDPAK; Alternate Manufacturer: None; Manufacturer: Infineon Technologies; Value1: ? ohm; ChMode: Enhancement; AEC Category: Q101; SizeZ_mm: 4.445; SizeY_mm: 10.16; VdsMax_V: 600V; SizeArea_mm2: 154.8892; IdsMax_A: 13A; SizeAreaWB_mm2: 209.6992; AEC Qualified: N; SizeX_mm: 15.245; Value2: 25 nC; QgTyp_nC: 25
Q2 = CMP-0079555-2: MOSFET, N-CH, 600 V, 9 A, DPAK; Manufacturer: Infineon Technologies; Alternate Manufacturer: None; SizeArea_mm2: 64.8114; Value1: ? ohm; IdsMax_A: 9A; ChType: N; Vgs_V: 20V; SizeX_mm: 9.91; AEC Category: Q101; SizeZ_mm: 2.29; VdsMax_V: 600V; Value2: 13 nC; ChMode: Enhancement; SizeAreaWB_mm2: 101.7114; QgTyp_nC: 13; SizeY_mm: 6.54
Q4 = CMP-0128225-1: Bipolar (BJT) Transistor NPN 125 V 1 A 155MHz 625 mW Surface Mount SOT-23-3; Manufacturer: Diodes Incorporated; AEC Qualified: No; IcRated_A: 1A; NPN: 1; SizeZ_mm: 1.1mm; Value: 125V; Vcesat1_V: 165mV; Emitter Base Voltage: 7V; Power_W: 625mW; Rthja Max: 200°C/W; Standoff Height: 0.013mm; TJmax_C: +150°C
Q5 = CMP-0090761-1: P-Channel 50V 130mA (Ta) 225mW (Ta) Surface Mount SOT-23-3 (TO-236); Manufacturer: On Semiconductor; IdsMax_A: -130mA; Number Of Channels: 1; Rthja Max: 556°C/W; Standoff Height: 0.01mm; Threshold Vgs Max: -2V; TJmax_C: +150°C; Pulse Drain Current: -520mA; Import Ts: 1521845730; VdsMax_V: -2.2V; Turn On Delay Time: 3.6ns; QgTyp_nC: 2.2nC @ -10V; Input Capacitace At Vds: 36pF @ 5V; Drain To Source Breakdown Voltage: -50V; Rdson45_ohm: 4.7; ChMode: False; AEC Qualified: No; Threshold Vgs Min: -0.9V; SizeZ_mm: 1.11mm; Ciiva Ids: 12912405; Vgs_V: 20V; Turn Off Delay Time: 12ns
Q6 = CMP-0000326-1: Transistor, PNP, 40 V, 0.2 A, SOT-23; Manufacturer: Diodes Inc.; TaMax_C: 150°C; Value2: 400; Value1: 0.2 A; Vcesat1_V: 250mV; SizeX_mm: 2.5; SizeY_mm: 3; TaMin_C: -55°C; IcRated_A: 200mA; CompType: BJT; SizeZ_mm: 1.1; SizeArea_mm2: 7.5; NPN: 0; Vceo_V: 40V; PNP: 1; AEC Category: Q101; SizeAreaWB_mm2: 14; U/M: EA
R1 R15 = CMP-0020812-2: RES, 2.2, 5%, 0.125 W, 0805; Manufacturer: Yageo America; Power_W: 125mW; TempCo: 200 ppm/C; Value_Code: 2R20; U/M: EA; Value: 2.2; EIA_Code: E24; SizeX_mm: 2; SizeY_mm: 1.25; SizeZ_mm: 1.45; Value2: 0.125W; SizeArea_mm2: 2.5; VDC_V: 150V; AEC Category: Q200
R2 R10 R17 R22 R32 = CMP-0021998-4: RES, 10.0 k, 1%, 0.1 W, AEC-Q200 Grade 0, 0603; PartNumber: CRCW060310K0FKEA; Manufacturer: Vishay-Dale; Value: 10.0k; Res_ohm: 10k; Value_Code: 10k0; Power_W: 100mW; Value2: 0.1W; VDC_V: 75V; TempCo: 100 ppm/C; SizeArea_mm2: 1.28; SizeX_mm: 1.6; SizeY_mm: 0.8; SizeZ_mm: 1; EIA_Code: E96; AEC Category: Q200; AEC Qualified: Y; AEC Grade: 0
R3 R18 = CMP-0020655-3: RES, 18, 5%, 0.125 W, AEC-Q200 Grade 0, 0805; Manufacturer: Panasonic; Power_W: 125mW; TempCo: 200 ppm/C; Value_Code: 18R0; Value: 18; EIA_Code: E24; SizeX_mm: 2; SizeY_mm: 1.25; SizeZ_mm: 1.45; Value2: 0.125W; SizeArea_mm2: 2.5; AEC Qualified: Y; VDC_V: 150V; AEC Category: Q200; AEC Grade: 0; SizeAreaWB_mm2: 6.75
R4 R5 = CMP-0015775-2: RES, 0.03, 1%, 2 W, 2512; PartNumber: CSRN2512FK30L0; Manufacturer: Stackpole Electronics Inc; Value: 0.03; Res_ohm: 30m; Value_Code: R030; Power_W: 2W; TempCo: 200 ppm/C; SizeArea_mm2: 20.16; SizeX_mm: 6.3; SizeY_mm: 3.2; SizeZ_mm: 0.71; EIA_Code: E96; U/M: EA; AEC Category: Q200
R6 R38 = CMP-0021990-4: RES, 100 k, 1%, 0.1 W, AEC-Q200 Grade 0, 0603; Manufacturer: Vishay-Dale; Power_W: 100mW; TempCo: 100 ppm/C; Value: 100k; EIA_Code: E96; SizeX_mm: 1.6; SizeY_mm: 0.8; SizeZ_mm: 1; Value2: 0.1W; SizeArea_mm2: 1.28; AEC Qualified: Y; VDC_V: 75V; AEC Category: Q200; AEC Grade: 0
R7 = CMP-0023068-4: RES, 390 k, 1%, 0.1 W, 0603; Manufacturer: Yageo; Power_W: 100mW; TempCo: 100 ppm/C; Value: 390k; SizeX_mm: 1.6; SizeY_mm: 0.8; SizeZ_mm: 1; Value2: 0.1W; SizeArea_mm2: 1.28; AEC Qualified: N; VDC_V: 75V; AEC Category: Q200; SizeAreaWB_mm2: 4.68
R8 R9 R14 = CMP-0018325-2: RES, 499 k, 1%, 0.25 W, 1206; Manufacturer: Yageo America; Power_W: 250mW; TempCo: 100 ppm/C; U/M: EA; Value: 499k; EIA_Code: E96; SizeX_mm: 3.2; SizeY_mm: 1.6; SizeZ_mm: 1.35; Value2: 0.25W; SizeArea_mm2: 5.12; VDC_V: 200V; AEC Category: Q200
R11 R16 R21 R43-R45 = CMP-0016729-3: RES, 1.37 M, 1%, 0.25 W, AEC-Q200 Grade 0, 1206; Manufacturer: Vishay-Dale; Power_W: 250mW; TempCo: 100 ppm/C; Value_Code: 1M37; Value: 1.37Meg; EIA_Code: E96; SizeX_mm: 3.2; SizeY_mm: 1.6; SizeZ_mm: 1.35; Value2: 0.25W; SizeArea_mm2: 5.12; AEC Qualified: Y; VDC_V: 200V; AEC Category: Q200; AEC Grade: 0
R12 R39 = CMP-0023152-5: RES, 4.75 k, 1%, 0.1 W, 0603; Manufacturer: Yageo; Power_W: 100mW; TempCo: 100 ppm/C; Value_Code: 4k75; Value: 4.75k; EIA_Code: E96; SizeX_mm: 1.6; SizeY_mm: 0.8; SizeZ_mm: 1; Value2: 0.1W; SizeArea_mm2: 1.28; AEC Qualified: N; VDC_V: 75V; AEC Category: Q200; SizeAreaWB_mm2: 4.68
R13 R34 = CMP-0022925-5: RES, 22.0 k, 1%, 0.1 W, 0603; Manufacturer: Yageo; Power_W: 100mW; TempCo: 100 ppm/C; Value_Code: 22k0; Value: 22.0k; Res_ohm: 22k; SizeX_mm: 1.6; SizeY_mm: 0.8; SizeZ_mm: 1; Value2: 0.1W; SizeArea_mm2: 1.28; AEC Qualified: N; VDC_V: 75V; AEC Category: Q200; SizeAreaWB_mm2: 4.68
R19 = CMP-0023050-5: RES, 35.7 k, 1%, 0.1 W, 0603; Manufacturer: Yageo; Power_W: 100mW; TempCo: 100 ppm/C; Value_Code: 35k7; Value: 35.7k; EIA_Code: E96; SizeX_mm: 1.6; SizeY_mm: 0.8; SizeZ_mm: 1; Value2: 0.1W; SizeArea_mm2: 1.28; AEC Qualified: N; VDC_V: 75V; AEC Category: Q200; SizeAreaWB_mm2: 4.68
R20 = CMP-0022691-3: RES, 20.0 k, 1%, 0.1 W, AEC-Q200 Grade 0, 0603; Manufacturer: Panasonic; Power_W: 100mW; TempCo: 100 ppm/C; Value_Code: 20k0; U/M: EA; Value: 20.0k; Res_ohm: 20k; SizeX_mm: 1.6; SizeY_mm: 0.8; SizeZ_mm: 1; Value2: 0.1W; SizeArea_mm2: 1.28; AEC Qualified: Y; VDC_V: 75V; AEC Grade: 0; AEC Category: Q200; EIA_Code: E96
R23 = CMP-0022899-4: RES, 1.00 M, 1%, 0.1 W, 0603; Manufacturer: Yageo; Power_W: 100mW; TempCo: 100 ppm/C; Value_Code: 1M00; Value: 1.00Meg; EIA_Code: E96; Res_ohm: 1M; SizeX_mm: 1.6; SizeY_mm: 0.8; SizeZ_mm: 1; Value2: 0.1W; SizeArea_mm2: 1.28; AEC Qualified: N; VDC_V: 75V; AEC Category: Q200; SizeAreaWB_mm2: 4.68
R24 = CMP-0022803-5: RES, 14.7 k, 1%, 0.1 W, 0603; Manufacturer: Yageo; Power_W: 100mW; TempCo: 100 ppm/C; Value_Code: 14k7; Value: 14.7k; EIA_Code: E96; SizeX_mm: 1.6; SizeY_mm: 0.8; SizeZ_mm: 1; Value2: 0.1W; SizeArea_mm2: 1.28; AEC Qualified: N; VDC_V: 75V; AEC Category: Q200; SizeAreaWB_mm2: 4.68
R25 R27 R29 = CMP-0016960-3: RES, 3.32 M, 1%, 0.25 W, AEC-Q200 Grade 0, 1206; Manufacturer: Vishay-Dale; Power_W: 250mW; TempCo: 100 ppm/C; Value_Code: 3M32; Value: 3.32Meg; EIA_Code: E96; SizeX_mm: 3.2; SizeY_mm: 1.6; SizeZ_mm: 1.35; Value2: 0.25W; SizeArea_mm2: 5.12; AEC Qualified: Y; VDC_V: 200V; AEC Category: Q200; AEC Grade: 0
R26 = CMP-0023224-5: RES, 63.4 k, 1%, 0.1 W, 0603; Manufacturer: Yageo; Power_W: 100mW; TempCo: 100 ppm/C; Value_Code: 63k4; Value: 63.4k; EIA_Code: E96; SizeX_mm: 1.6; SizeY_mm: 0.8; SizeZ_mm: 1; Value2: 0.1W; SizeArea_mm2: 1.28; AEC Qualified: N; VDC_V: 75V; AEC Category: Q200; SizeAreaWB_mm2: 4.68
R28 = CMP-0021991-4: RES, 100, 1%, 0.1 W, AEC-Q200 Grade 0, 0603; PartNumber: CRCW0603100RFKEA; Manufacturer: Vishay-Dale; Value: 100; Value_Code: 100R; Power_W: 100mW; Value2: 0.1W; VDC_V: 75V; TempCo: 100 ppm/C; EIA_Code: E96; AEC Category: Q200; AEC Grade: 0; AEC Qualified: Y; SizeArea_mm2: 1.28; SizeX_mm: 1.6; SizeY_mm: 0.8; SizeZ_mm: 1
R30 R31 = CMP-0074631-2: RES, 18.0 k, 1%, 0.125 W, 0805; Manufacturer: Yageo America; Power_W: 125mW; Green_Lifecycle: Active; TempCo: 100 ppm/C; Value_Code: 18k0; Green_REACh: Passed; U/M: EA; Value: 18.0k; Res_ohm: 18k; SizeX_mm: 2.0; SizeY_mm: 1.25; SizeZ_mm: 1.45; Value2: 0.125W; SizeArea_mm2: 2.5; AEC Qualified: N; AEC Category: Q200
R33 = CMP-0022812-4: RES, 158 k, 1%, 0.1 W, 0603; Manufacturer: Yageo; Power_W: 100mW; TempCo: 100 ppm/C; Value: 158k; EIA_Code: E96; SizeX_mm: 1.6; SizeY_mm: 0.8; SizeZ_mm: 1; Value2: 0.1W; SizeArea_mm2: 1.28; AEC Qualified: N; VDC_V: 75V; AEC Category: Q200; SizeAreaWB_mm2: 4.68
R35 R47 = CMP-0023132-5: RES, 47.5 k, 1%, 0.1 W, 0603; Manufacturer: Yageo; Power_W: 100mW; TempCo: 100 ppm/C; Value_Code: 47k5; Value: 47.5k; EIA_Code: E96; SizeX_mm: 1.6; SizeY_mm: 0.8; SizeZ_mm: 1; Value2: 0.1W; SizeArea_mm2: 1.28; AEC Qualified: N; VDC_V: 75V; AEC Category: Q200; SizeAreaWB_mm2: 4.68
R36 = CMP-0022901-4: RES, 200 k, 1%, 0.1 W, 0603; Manufacturer: Yageo; Power_W: 100mW; TempCo: 100 ppm/C; Value: 200k; EIA_Code: E96; SizeX_mm: 1.6; SizeY_mm: 0.8; SizeZ_mm: 1; Value2: 0.1W; AEC Qualified: N; VDC_V: 75V; AEC Category: Q200; SizeArea_mm2: 1.28; SizeAreaWB_mm2: 4.68
R37 = CMP-0022846-4: RES, 182 k, 1%, 0.1 W, 0603; Manufacturer: Yageo; Power_W: 100mW; TempCo: 100 ppm/C; Value: 182k; EIA_Code: E96; SizeX_mm: 1.6; SizeY_mm: 0.8; SizeZ_mm: 1; Value2: 0.1W; SizeArea_mm2: 1.28; AEC Qualified: N; VDC_V: 75V; AEC Category: Q200; SizeAreaWB_mm2: 4.68
R40 = CMP-0022971-4: RES, 287 k, 1%, 0.1 W, 0603; Manufacturer: Yageo; Power_W: 100mW; TempCo: 100 ppm/C; Value: 287k; EIA_Code: E96; SizeX_mm: 1.6; SizeY_mm: 0.8; SizeZ_mm: 1; Value2: 0.1W; SizeArea_mm2: 1.28; AEC Qualified: N; VDC_V: 75V; AEC Category: Q200; SizeAreaWB_mm2: 4.68
R41 = CMP-0022958-5: RES, 26.7 k, 1%, 0.1 W, 0603; Manufacturer: Yageo; Power_W: 100mW; TempCo: 100 ppm/C; Value_Code: 26k7; Value: 26.7k; EIA_Code: E96; SizeX_mm: 1.6; SizeY_mm: 0.8; SizeZ_mm: 1; Value2: 0.1W; SizeArea_mm2: 1.28; AEC Qualified: N; VDC_V: 75V; AEC Category: Q200; SizeAreaWB_mm2: 4.68
R42 = CMP-0023285-5: RES, 80.6 k, 1%, 0.1 W, 0603; Manufacturer: Yageo; Power_W: 100mW; TempCo: 100 ppm/C; Value_Code: 80k6; EIA_Code: E96; SizeX_mm: 1.6; SizeY_mm: 0.8; SizeZ_mm: 1; Value2: 0.1W; Value: 80.6k; SizeArea_mm2: 1.28; AEC Qualified: N; VDC_V: 75V; AEC Category: Q200; SizeAreaWB_mm2: 4.68
R46 = CMP-0023126-5: RES, 46.4 k, 1%, 0.1 W, 0603; Manufacturer: Yageo; Power_W: 100mW; TempCo: 100 ppm/C; Value_Code: 46k4; Value: 46.4k; EIA_Code: E96; SizeX_mm: 1.6; SizeY_mm: 0.8; SizeZ_mm: 1; Value2: 0.1W; SizeArea_mm2: 1.28; AEC Qualified: N; VDC_V: 75V; AEC Category: Q200; SizeAreaWB_mm2: 4.68
R200 = CMP-0017284-3: RES, 10.0 k, 1%, 0.25 W, AEC-Q200 Grade 0, 1206; Manufacturer: Panasonic; Power_W: 250mW; TempCo: 100 ppm/C; Value_Code: 10k0; Value: 10.0k; EIA_Code: E96; Res_ohm: 10k; SizeX_mm: 3.2; SizeY_mm: 1.6; SizeZ_mm: 1.35; Value2: 0.25W; SizeArea_mm2: 5.12; AEC Qualified: Y; VDC_V: 200V; AEC Category: Q200; AEC Grade: 0; SizeAreaWB_mm2: 10.92
RT1 = CMP-0002554-2: Thermistor NTC, 22 ohm, 20%, 15x7mm; Manufacturer: TDK; TaMax_C: 170°C; SizeX_mm: 15; SizeY_mm: 7.5; TaMin_C: -55°C; Power_W: 3.1W; SizeZ_mm: 47; SizeArea_mm2: 112.5; SizeAreaWB_mm2: 161.5; U/M: EA
RV1 = CMP-0002101-2: Varistor, 275VAC, 1200A, SMD; Manufacturer: Littelfuse
TP1 TP2 TP17 = CMP-0055137-2: Test Point, Miniature, Red, TH; Manufacturer: Keystone Electronics; Green_REACh: Passed; Green_Lifecycle: Active; ContactFinish: Silver; CNHeader: FALSE; CT: TRUE
TP3 TP6 TP10-TP14 TP16 TP18-TP22 = CMP-0055141-2: Test Point, Miniature, Yellow, TH; Manufacturer: Keystone Electronics; CT: TRUE; ContactFinish: Silver; Green_Lifecycle: Active; CNHeader: FALSE; Green_REACh: Passed
TP4 TP7 TP9 TP15 = CMP-0055138-2: Test Point, Miniature, Black, TH; Manufacturer: Keystone Electronics; ContactFinish: Silver; CNHeader: FALSE; Green_Lifecycle: Active; Green_REACh: Passed; CT: TRUE
TP5 TP8 = CMP-0055139-2: Test Point, Miniature, White, TH; Manufacturer: Keystone Electronics; ContactFinish: Silver; Green_REACh: Passed; CT: TRUE; Green_Lifecycle: Active; CNHeader: FALSE
U1 = CMP-0089002-1: Dual Rail-to-rail Comparator with push-pull outputs, 8-SOIC; Manufacturer: Texas Instruments; SizeZ_mm: 1.75mm; AEC Qualified: No
U2 = CMP-0033016-1: Precision Micropower Shunt Voltage Reference, 1% accuracy, 5 V, 15 ppm / degC, 15 mA, -40 to 125 degC, 3-pin SOT-23 (DBZ), Green (RoHS & no Sb/Br); Manufacturer: Texas Instruments; Rating: Catalog; Temp Coeff(Typ)(ppm/ degree C): 15; Initial Accuracy @ 25/deg C(%): 1; Temp Coeff(Max)(ppm/ degree C): 150; VO(V): 5; Min Iz for Regulation(uA): 79
U3 = CMP-0861100-1: Natural Interleaving Transition Mode PFC Controller with High Light Load Efficiency Supporting High-Frequency Switching up-to 1MHz, D0016A (SOIC-16); Manufacturer: Texas Instruments; SizeArea_mm2: 59.4; SizeX_mm: 6; SizeZ_mm: 1.75; SizeAreaWB_mm2: 95.2; AEC Category: Q200; CompType: IC; AEC Qualified: N; SizeY_mm: 9.9
U4 U5 = CMP-0006172-3: Optocoupler, 5.3 kV, 63-125% CTR, SMT; Manufacturer: Vishay-Semiconductor; CTR (Max): 125%; CTR (Min): 63%; Voltage_Isolation_Vrms: 5.3kV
